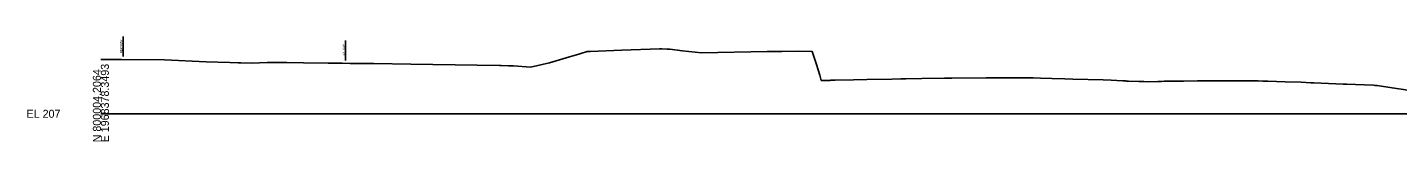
# Model space of a CAD drawing. Extents: x 1979833 to 1982361, y 790388 to 810009.
# Drawn here: x 1979832.9 to 1980312.1, y 802888 to 802924.8 of the extents above; entities that cross this region are included whole.
import ezdxf

# ---------------------------------------------------------------- set-up
doc = ezdxf.new("R2010")
doc.units = 0
for name, color, linetype in [('Default', 7, 'Continuous'), ('RD_GPK_XS_Cell', 7, 'Continuous'), ('RD_XS_ExGround', 7, 'Continuous'), ('RD_XS_ExRW', 7, 'Continuous'), ('RD_XS_NewRW', 7, 'Continuous')]:
    doc.layers.add(name, color=color, linetype=linetype)

msp = doc.modelspace()

# ---------------------------------------------------------------- linework, layer by layer
at = {"layer": 'RD_GPK_XS_Cell'}
msp.add_line((1979858.57, 802897.73), (1980358.57, 802897.73), dxfattribs=at)
at = {"layer": 'RD_XS_ExGround'}
msp.add_lwpolyline([(1979858.57, 802916.68), (1979861.97, 802916.72), (1979862.49, 802916.73), (1979865.78, 802916.77), (1979880.86, 802916.65), (1979895.42, 802915.95), (1979903.73, 802915.65), (1979906.54, 802915.58), (1979907.52, 802915.61), (1979911.42, 802915.5), (1979916.78, 802915.68), (1979918.62, 802915.68), (1979923.59, 802915.69), (1979929.46, 802915.6), (1979938.08, 802915.43), (1979940.5, 802915.42), (1979942.93, 802915.39), (1979945.77, 802915.35), (1979951.29, 802915.32), (1979954.04, 802915.35), (1979966.99, 802915.04), (1979974.73, 802914.96), (1979998.03, 802914.6), (1979998.63, 802914.6), (1980001.14, 802914.53), (1980002.92, 802914.49), (1980008.8, 802914.02), (1980015.46, 802915.6), (1980022.53, 802917.71), (1980025.79, 802918.61), (1980026.45, 802918.79), (1980028.62, 802919.52), (1980029.76, 802919.57), (1980040.83, 802919.97), (1980054.02, 802920.44), (1980054.74, 802920.47), (1980056.67, 802920.36), (1980057.63, 802920.29), (1980062.05, 802919.79), (1980068.71, 802919.04), (1980091.62, 802919.53), (1980096.79, 802919.58), (1980102.72, 802919.6), (1980107.34, 802919.53), (1980108.88, 802914.92), (1980110.03, 802911.24), (1980110.56, 802909.41), (1980111.82, 802909.42), (1980113.5, 802909.43), (1980113.89, 802909.53), (1980115.39, 802909.54), (1980121.83, 802909.61), (1980126.53, 802909.69), (1980135.28, 802909.86), (1980138.44, 802909.92), (1980139.43, 802909.93), (1980140.18, 802909.95), (1980145.76, 802910.03), (1980153.6, 802910.14), (1980156.27, 802910.17), (1980168.22, 802910.33), (1980174.53, 802910.32), (1980179.31, 802910.33), (1980181.76, 802910.32), (1980182.85, 802910.32), (1980184.71, 802910.3), (1980187.26, 802910.21), (1980191.2, 802910.07), (1980195.77, 802909.96), (1980198.6, 802909.88), (1980209.19, 802909.56), (1980211.9, 802909.48), (1980213.99, 802909.41), (1980215.98, 802909.3), (1980216.94, 802909.26), (1980217.33, 802909.18), (1980217.96, 802909.15), (1980221.64, 802909.02), (1980223.39, 802908.99), (1980225.17, 802908.96), (1980228.28, 802908.98), (1980229.28, 802908.99), (1980229.52, 802909.08), (1980230.54, 802909.1), (1980233.01, 802909.16), (1980237.29, 802909.2), (1980242.19, 802909.24), (1980245.23, 802909.27), (1980247.94, 802909.29), (1980251.85, 802909.29), (1980255.18, 802909.29), (1980258.38, 802909.27), (1980263.35, 802909.24), (1980265.01, 802909.18), (1980266.79, 802909.11), (1980272.76, 802908.93), (1980278.47, 802908.75), (1980281.85, 802908.61), (1980282.81, 802908.57), (1980293.08, 802908.15), (1980294.36, 802908.1), (1980297.47, 802907.98), (1980303.69, 802907.76), (1980304.19, 802907.62), (1980304.57, 802907.61), (1980305.02, 802907.61), (1980310.27, 802906.86), (1980315.78, 802906.05)], dxfattribs=at)
at = {"layer": 'RD_XS_ExRW'}
msp.add_line((1979944.16, 802916.37), (1979944.16, 802923.37), dxfattribs=at)
at = {"layer": 'RD_XS_NewRW'}
msp.add_line((1979866.33, 802917.76), (1979866.33, 802924.76), dxfattribs=at)

# ---------------------------------------------------------------- texts
at = {"layer": 'Default'}
msp.add_text('-', height=0.0001, dxfattribs=at).set_placement((1979858.57, 802897.73))
at = {"layer": 'RD_GPK_XS_Cell'}
for s, p in [('N 800004.2064', (1979858.57, 802887.73)), ('E 1968378.3493', (1979861.37, 802887.73))]:
    msp.add_text(s, height=2.8, rotation=90, dxfattribs=at).set_placement(p)
msp.add_text('EL 207', height=2.8, dxfattribs=at).set_placement((1979832.57, 802896.33))
at = {"layer": 'RD_XS_ExRW'}
msp.add_text('EX. R/W ', height=0.75, rotation=90, dxfattribs=at).set_placement((1979943.86, 802918.05))
at = {"layer": 'RD_XS_NewRW'}
msp.add_text('NEW R/W ', height=0.75, rotation=90, dxfattribs=at).set_placement((1979866.04, 802918.91))

doc.saveas('drawing.dxf')
